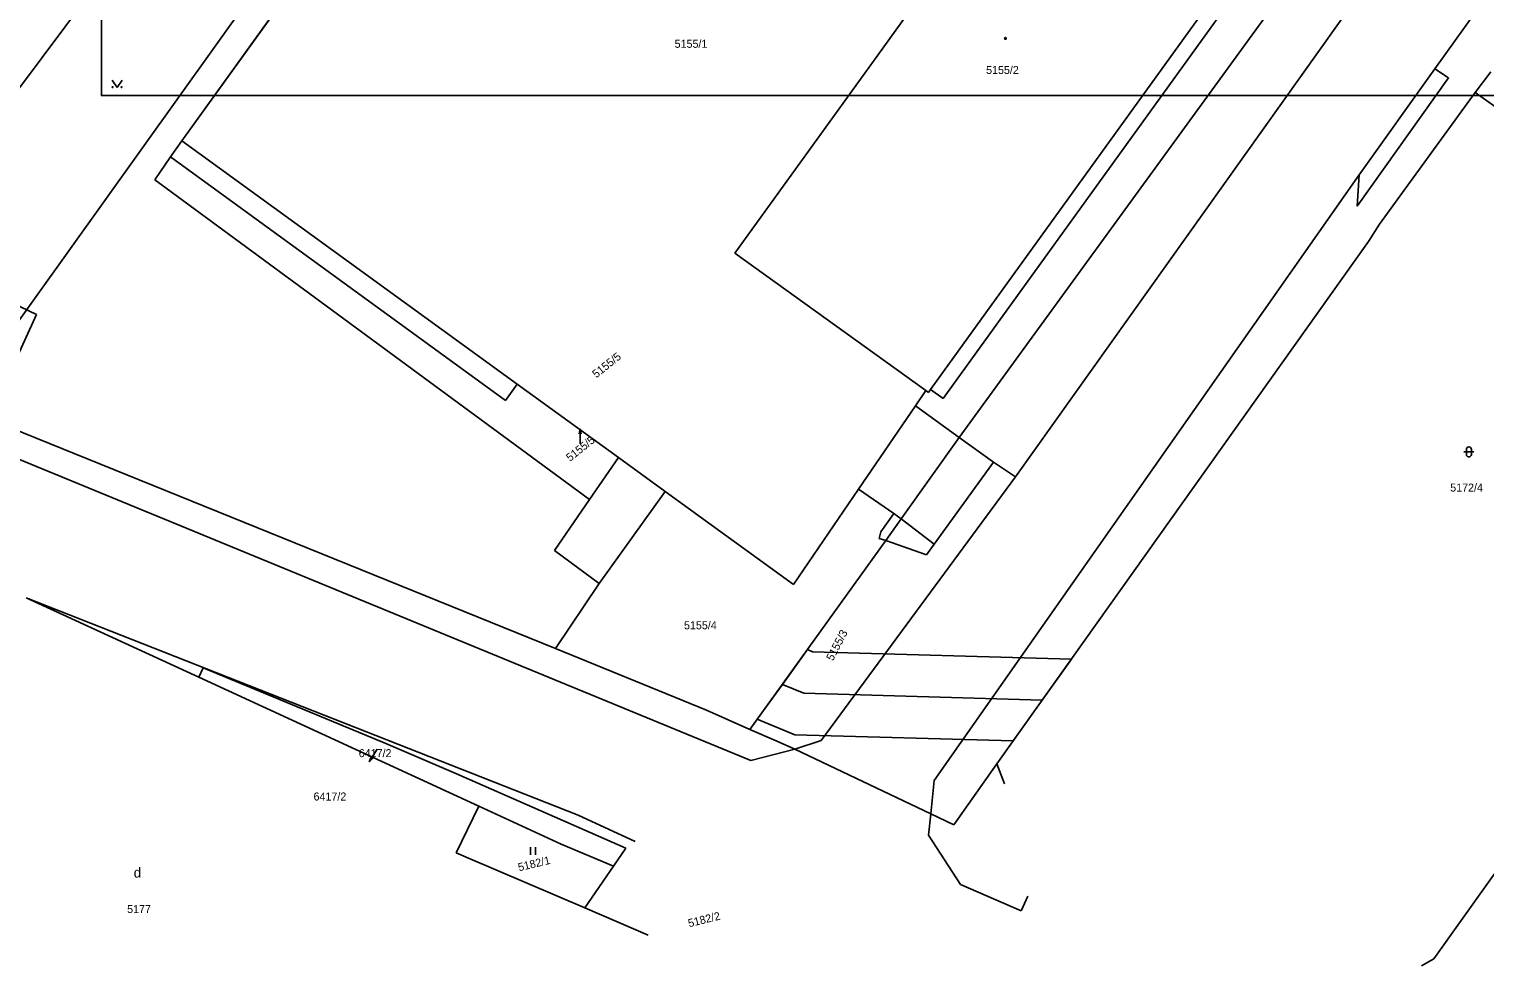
# Model space of a CAD drawing. Extents: x -400488 to -400124, y -1251493 to -1251223.
# Drawn here: x -400401.8 to -400314.4, y -1251493.2 to -1251437 of the extents above; entities that cross this region are included whole.
import ezdxf

# ---------------------------------------------------------------- set-up
doc = ezdxf.new("R2010")
doc.units = 0
doc.layers.add('Level 3', color=7, linetype='Continuous')
doc.layers.add('Level 63', color=7, linetype='Continuous')

msp = doc.modelspace()

# ---------------------------------------------------------------- linework, layer by layer
at = {"layer": 'Level 3'}
msp.add_lwpolyline([(-400397.431, -1251233.087), (-400250.431, -1251233.087), (-400250.431, -1251440.987), (-400397.431, -1251440.987)], close=True, dxfattribs=at)
at = {"layer": 'Level 63'}
for p, q in [((-400390.33, -1251424.43), (-400408.31, -1251448.5)), ((-400406.06, -1251459.62), (-400382.37, -1251426.48)), ((-400380.61, -1251427.03), (-400392.61, -1251443.7)), ((-400392.61, -1251443.7), (-400380.61, -1251427.03)), ((-400350.86, -1251438.57), (-400342.33, -1251426.66)), ((-400342.33, -1251426.66), (-400350.86, -1251438.57)), ((-400345.99, -1251461.49), (-400323.3, -1251430.31)), ((-400323.3, -1251430.31), (-400345.99, -1251461.49)), ((-400312.95, -1251433.09), (-400317.46, -1251439.39)), ((-400342.61, -1251463.85), (-400321.51, -1251434.24)), ((-400321.51, -1251434.24), (-400342.61, -1251463.85)), ((-400330.84, -1251435.27), (-400347.7, -1251458.61)), ((-400330.08, -1251435.81), (-400346.94, -1251459.15)), ((-400346.94, -1251459.15), (-400330.08, -1251435.81)), ((-400359.17, -1251450.07), (-400350.86, -1251438.57)), ((-400350.86, -1251438.57), (-400359.17, -1251450.07)), ((-400317.46, -1251439.39), (-400321.99, -1251445.75)), ((-400316.64, -1251439.93), (-400317.46, -1251439.39)), ((-400396.79, -1251440.06), (-400396.49, -1251440.51)), ((-400396.49, -1251440.51), (-400396.19, -1251440.06)), ((-400322.12, -1251447.61), (-400316.64, -1251439.93)), ((-400314.1, -1251439.56), (-400315.03, -1251440.81)), ((-400315.03, -1251440.81), (-400314.1, -1251439.56)), ((-400315.03, -1251440.81), (-400320.78, -1251448.7)), ((-400320.78, -1251448.7), (-400315.03, -1251440.81)), ((-400315.03, -1251440.81), (-400309.14, -1251445)), ((-400392.61, -1251443.7), (-400393.28, -1251444.67)), ((-400393.28, -1251444.67), (-400392.61, -1251443.7)), ((-400392.61, -1251443.7), (-400372.49, -1251458.29)), ((-400392.61, -1251443.7), (-400372.49, -1251458.29)), ((-400393.28, -1251444.67), (-400394.22, -1251446.05)), ((-400394.22, -1251446.05), (-400393.28, -1251444.67)), ((-400393.28, -1251444.67), (-400373.19, -1251459.27)), ((-400373.19, -1251459.27), (-400393.28, -1251444.67)), ((-400393.28, -1251444.67), (-400373.19, -1251459.27)), ((-400419.41, -1251445.51), (-400401.33, -1251454.11)), ((-400394.22, -1251446.05), (-400368.15, -1251465.21)), ((-400368.15, -1251465.21), (-400394.22, -1251446.05)), ((-400347.49, -1251482.07), (-400321.99, -1251445.75)), ((-400321.99, -1251445.75), (-400322.12, -1251447.61)), ((-400320.78, -1251448.7), (-400321.44, -1251449.73)), ((-400321.44, -1251449.73), (-400320.78, -1251448.7)), ((-400321.44, -1251449.73), (-400343.72, -1251481.08)), ((-400343.72, -1251481.08), (-400321.44, -1251449.73)), ((-400359.44, -1251450.44), (-400359.17, -1251450.07)), ((-400359.17, -1251450.07), (-400359.44, -1251450.44)), ((-400347.98, -1251458.68), (-400359.44, -1251450.44)), ((-400359.44, -1251450.44), (-400347.98, -1251458.68)), ((-400401.33, -1251454.11), (-400417.35, -1251488.99)), ((-400373.19, -1251459.27), (-400372.49, -1251458.29)), ((-400372.49, -1251458.29), (-400373.19, -1251459.27)), ((-400373.19, -1251459.27), (-400372.49, -1251458.29)), ((-400366.41, -1251462.7), (-400372.49, -1251458.29)), ((-400372.49, -1251458.29), (-400366.41, -1251462.7)), ((-400347.98, -1251458.68), (-400348.6, -1251459.59)), ((-400348.6, -1251459.59), (-400347.98, -1251458.68)), ((-400347.83, -1251458.79), (-400347.98, -1251458.68)), ((-400347.98, -1251458.68), (-400347.83, -1251458.79)), ((-400347.7, -1251458.61), (-400347.83, -1251458.79)), ((-400347.83, -1251458.79), (-400347.7, -1251458.61)), ((-400346.94, -1251459.15), (-400347.7, -1251458.61)), ((-400347.7, -1251458.61), (-400346.94, -1251459.15)), ((-400348.6, -1251459.59), (-400352.02, -1251464.6)), ((-400348.6, -1251459.59), (-400352.02, -1251464.6)), ((-400348.6, -1251459.59), (-400345.99, -1251461.49)), ((-400345.99, -1251461.49), (-400348.6, -1251459.59)), ((-400370.19, -1251474.16), (-400406.06, -1251459.62)), ((-400406.06, -1251459.62), (-400370.19, -1251474.16)), ((-400358.48, -1251480.87), (-400406.5, -1251461.12)), ((-400368.72, -1251460.97), (-400368.78, -1251461.27)), ((-400368.72, -1251461.87), (-400368.72, -1251460.97)), ((-400368.66, -1251461.27), (-400368.72, -1251460.97)), ((-400345.99, -1251461.49), (-400349.47, -1251466.38)), ((-400349.47, -1251466.38), (-400345.99, -1251461.49)), ((-400345.99, -1251461.49), (-400343.93, -1251462.98)), ((-400343.93, -1251462.98), (-400345.99, -1251461.49)), ((-400315.56, -1251462.21), (-400315.56, -1251462.51)), ((-400315.26, -1251462.21), (-400315.26, -1251462.51)), ((-400368.15, -1251465.21), (-400366.41, -1251462.7)), ((-400368.15, -1251465.21), (-400366.41, -1251462.7)), ((-400366.41, -1251462.7), (-400368.15, -1251465.21)), ((-400366.41, -1251462.7), (-400363.61, -1251464.73)), ((-400366.41, -1251462.7), (-400363.61, -1251464.73)), ((-400343.93, -1251462.98), (-400347.48, -1251467.89)), ((-400343.93, -1251462.98), (-400347.48, -1251467.89)), ((-400343.93, -1251462.98), (-400342.61, -1251463.85)), ((-400342.61, -1251463.85), (-400343.93, -1251462.98)), ((-400315.71, -1251462.36), (-400315.11, -1251462.36)), ((-400354.26, -1251479.68), (-400342.61, -1251463.85)), ((-400342.61, -1251463.85), (-400354.26, -1251479.68)), ((-400367.58, -1251470.26), (-400363.61, -1251464.73)), ((-400363.61, -1251464.73), (-400367.58, -1251470.26)), ((-400367.58, -1251470.26), (-400363.61, -1251464.73)), ((-400355.92, -1251470.31), (-400363.61, -1251464.73)), ((-400363.61, -1251464.73), (-400355.92, -1251470.31)), ((-400352.02, -1251464.6), (-400355.92, -1251470.31)), ((-400355.92, -1251470.31), (-400352.02, -1251464.6)), ((-400349.9, -1251466.05), (-400352.02, -1251464.6)), ((-400352.02, -1251464.6), (-400349.9, -1251466.05)), ((-400368.15, -1251465.21), (-400370.26, -1251468.28)), ((-400370.26, -1251468.28), (-400368.15, -1251465.21)), ((-400350.69, -1251467.16), (-400349.9, -1251466.05)), ((-400349.9, -1251466.05), (-400350.69, -1251467.16)), ((-400349.47, -1251466.38), (-400350.39, -1251467.67)), ((-400350.39, -1251467.67), (-400349.47, -1251466.38)), ((-400349.9, -1251466.05), (-400349.47, -1251466.38)), ((-400349.47, -1251466.38), (-400347.48, -1251467.89)), ((-400350.79, -1251467.56), (-400350.69, -1251467.16)), ((-400350.69, -1251467.16), (-400350.79, -1251467.56)), ((-400370.26, -1251468.28), (-400367.58, -1251470.26)), ((-400367.58, -1251470.26), (-400370.26, -1251468.28)), ((-400350.39, -1251467.67), (-400358.53, -1251479.01)), ((-400358.53, -1251479.01), (-400350.39, -1251467.67)), ((-400350.39, -1251467.67), (-400350.79, -1251467.56)), ((-400350.79, -1251467.56), (-400350.39, -1251467.67)), ((-400347.95, -1251468.54), (-400350.39, -1251467.67)), ((-400347.48, -1251467.89), (-400347.95, -1251468.54)), ((-400347.48, -1251467.89), (-400347.95, -1251468.54)), ((-400367.58, -1251470.26), (-400370.19, -1251474.16)), ((-400370.19, -1251474.16), (-400367.58, -1251470.26)), ((-400401.94, -1251471.11), (-400391.59, -1251475.88)), ((-400368.83, -1251484.14), (-400401.94, -1251471.11)), ((-400391.59, -1251475.88), (-400401.94, -1251471.11)), ((-400370.19, -1251474.16), (-400361.14, -1251477.85)), ((-400361.14, -1251477.85), (-400370.19, -1251474.16)), ((-400356.59, -1251476.31), (-400355.09, -1251474.22)), ((-400355.09, -1251474.22), (-400354.78, -1251474.35)), ((-400354.78, -1251474.35), (-400339.25, -1251474.79)), ((-400317.51, -1251492.77), (-400304.46, -1251474.44)), ((-400391.59, -1251475.88), (-400391.32, -1251475.31)), ((-400391.32, -1251475.31), (-400391.59, -1251475.88)), ((-400391.32, -1251475.31), (-400380.38, -1251479.86)), ((-400380.38, -1251479.86), (-400391.32, -1251475.31)), ((-400339.25, -1251474.79), (-400341, -1251477.25)), ((-400391.59, -1251475.88), (-400374.8, -1251483.61)), ((-400374.8, -1251483.61), (-400391.59, -1251475.88)), ((-400358.09, -1251478.39), (-400356.59, -1251476.31)), ((-400356.59, -1251476.31), (-400355.31, -1251476.84)), ((-400355.31, -1251476.84), (-400341, -1251477.25)), ((-400361.14, -1251477.85), (-400358.53, -1251479.01)), ((-400358.53, -1251479.01), (-400361.14, -1251477.85)), ((-400341, -1251477.25), (-400342.74, -1251479.7)), ((-400355.84, -1251479.33), (-400358.09, -1251478.39)), ((-400358.53, -1251479.01), (-400356.97, -1251479.7)), ((-400356.97, -1251479.7), (-400358.53, -1251479.01)), ((-400355.85, -1251480.19), (-400354.26, -1251479.68)), ((-400354.26, -1251479.68), (-400355.85, -1251480.19)), ((-400342.74, -1251479.7), (-400355.84, -1251479.33)), ((-400380.89, -1251480.19), (-400381.37, -1251480.951)), ((-400380.38, -1251479.86), (-400376.17, -1251481.65)), ((-400376.17, -1251481.65), (-400380.38, -1251479.86)), ((-400355.85, -1251480.19), (-400358.48, -1251480.87)), ((-400356.97, -1251479.7), (-400355.85, -1251480.19)), ((-400355.85, -1251480.19), (-400356.97, -1251479.7)), ((-400347.69, -1251484.06), (-400355.85, -1251480.19)), ((-400355.85, -1251480.19), (-400347.69, -1251484.06)), ((-400381.261, -1251480.665), (-400381.37, -1251480.951)), ((-400381.37, -1251480.951), (-400381.159, -1251480.73)), ((-400343.72, -1251481.08), (-400345.2, -1251483.16)), ((-400345.2, -1251483.16), (-400343.72, -1251481.08)), ((-400343.72, -1251481.08), (-400343.27, -1251482.27)), ((-400376.17, -1251481.65), (-400365.97, -1251486.12)), ((-400365.97, -1251486.12), (-400376.17, -1251481.65)), ((-400347.69, -1251484.06), (-400347.49, -1251482.07)), ((-400345.2, -1251483.16), (-400346.31, -1251484.72)), ((-400346.31, -1251484.72), (-400345.2, -1251483.16)), ((-400376.15, -1251486.41), (-400374.8, -1251483.61)), ((-400374.8, -1251483.61), (-400376.15, -1251486.41)), ((-400374.8, -1251483.61), (-400369.86, -1251485.88)), ((-400369.86, -1251485.88), (-400374.8, -1251483.61)), ((-400347.69, -1251484.06), (-400347.82, -1251485.35)), ((-400346.31, -1251484.72), (-400347.69, -1251484.06)), ((-400347.69, -1251484.06), (-400346.31, -1251484.72)), ((-400365.42, -1251485.73), (-400368.83, -1251484.14)), ((-400347.82, -1251485.35), (-400345.9, -1251488.3)), ((-400375.42, -1251486.72), (-400376.15, -1251486.41)), ((-400376.15, -1251486.41), (-400375.42, -1251486.72)), ((-400371.695, -1251486.525), (-400371.695, -1251486.075)), ((-400371.395, -1251486.525), (-400371.395, -1251486.075)), ((-400369.86, -1251485.88), (-400366.72, -1251487.2)), ((-400366.72, -1251487.2), (-400369.86, -1251485.88)), ((-400366.72, -1251487.2), (-400365.97, -1251486.12)), ((-400365.97, -1251486.12), (-400366.72, -1251487.2)), ((-400375.42, -1251486.72), (-400368.44, -1251489.71)), ((-400368.44, -1251489.71), (-400375.42, -1251486.72)), ((-400368.44, -1251489.71), (-400366.72, -1251487.2)), ((-400366.72, -1251487.2), (-400368.44, -1251489.71)), ((-400345.9, -1251488.3), (-400342.26, -1251489.88)), ((-400341.87, -1251489.01), (-400342.26, -1251489.88)), ((-400364.63, -1251491.34), (-400368.44, -1251489.71)), ((-400368.44, -1251489.71), (-400364.63, -1251491.34)), ((-400318.25, -1251493.19), (-400317.51, -1251492.77))]:
    msp.add_line(p, q, dxfattribs=at)
for centre, radius in [((-400343.21, -1251437.556), 0.054), ((-400396.76, -1251440.48), 0.03), ((-400396.22, -1251440.48), 0.03)]:
    msp.add_circle(centre, radius, dxfattribs=at)
for centre, start, end in [((-400315.41, -1251462.21), 0, 180), ((-400315.41, -1251462.51), 180, 0)]:
    msp.add_arc(centre, 0.15, start, end, dxfattribs=at)

# ---------------------------------------------------------------- texts
for s, height, p in [('5155/1', 0.48, (-400363.05, -1251438.12)), ('5155/2', 0.48, (-400344.368, -1251439.69)), ('5172/4', 0.48, (-400316.53, -1251464.74)), ('5155/4', 0.48, (-400362.488, -1251473)), ('6417/2', 0.48, (-400381.998, -1251480.67)), ('6417/2', 0.48, (-400384.708, -1251483.27)), ('d', 0.6, (-400395.493, -1251487.89)), ('5177', 0.48, (-400395.891, -1251490.02))]:
    msp.add_text(s, height=height, dxfattribs=at).set_placement(p)
for s, rotation, p in [('5155/5', 38.4, (-400367.754, -1251457.951)), ('5155/5', 38.4, (-400369.324, -1251462.961)), ('5155/3', 62.58, (-400353.559, -1251474.932)), ('5182/1', 13.44, (-400372.381, -1251487.519)), ('5182/2', 14.01, (-400362.179, -1251490.877))]:
    msp.add_text(s, height=0.48, rotation=rotation, dxfattribs=at).set_placement(p)

doc.saveas('drawing.dxf')
